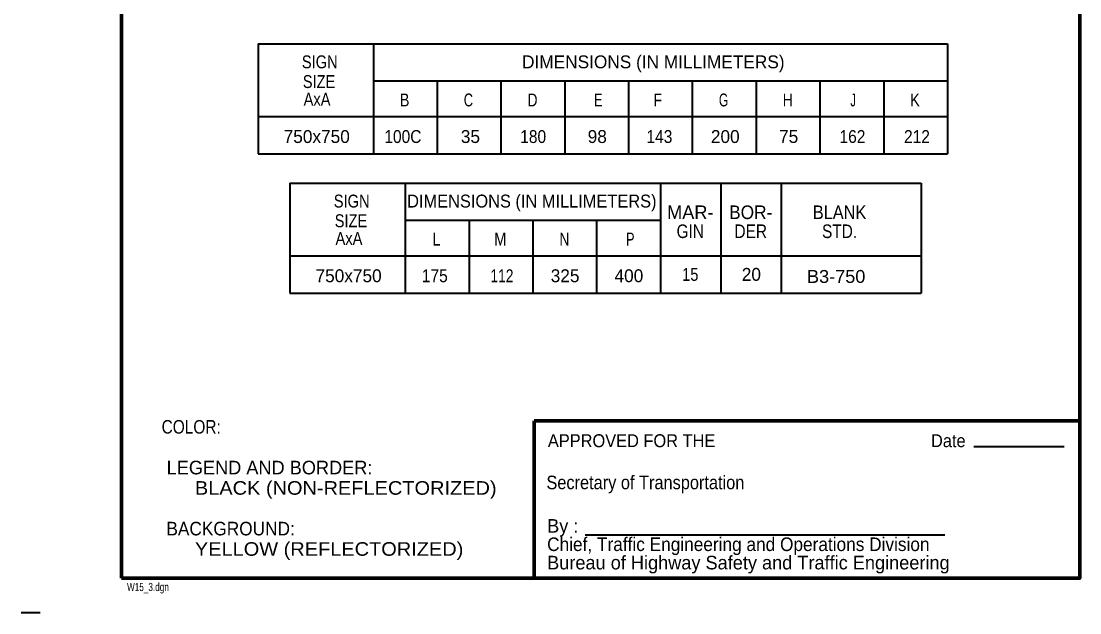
# Model space of a CAD drawing. Extents: x -0.018 to 0.195, y -0.006 to 0.263.
# Drawn here: x -0.0185 to 0.1765, y -0.0064 to 0.1026 of the extents above; entities that cross this region are included whole.
import ezdxf
from ezdxf.enums import TextEntityAlignment as Align

# ---------------------------------------------------------------- set-up
doc = ezdxf.new("R2010")
doc.units = 0
doc.header["$LTSCALE"] = 0.00096
doc.layers.add('1', color=7, linetype='Continuous', lineweight=25)
doc.layers.add('3', color=7, linetype='Continuous', lineweight=35)

msp = doc.modelspace()

# ---------------------------------------------------------------- linework, layer by layer
at = {"layer": '1', "lineweight": 70}
for q in [(0.1765, 0.029), (0.076, 0)]:
    msp.add_line((0.076, 0.029), q, dxfattribs=at)
at = {"layer": '1', "lineweight": 35}
for p, q in [((0.157, 0.02425), (0.17363, 0.02425)), ((0.08538, 0.008), (0.15163, 0.008)), ((-0.015, -0.00637), (-0.0185, -0.00637))]:
    msp.add_line(p, q, dxfattribs=at)
at = {"layer": '1', "lineweight": 70}
msp.add_lwpolyline([(0, 0), (0.1765, 0), (0.1765, 0.2565), (0, 0.2565)], close=True, dxfattribs=at)
at = {"layer": '3'}
for p, q in [((0.02513, 0.09838), (0.15213, 0.09838)), ((0.02513, 0.09838), (0.02513, 0.07812)), ((0.04637, 0.09838), (0.04637, 0.07812)), ((0.15213, 0.09838), (0.15213, 0.07812)), ((0.15213, 0.0915), (0.04637, 0.0915)), ((0.05813, 0.0915), (0.05813, 0.07812)), ((0.06988, 0.0915), (0.06988, 0.07812)), ((0.08163, 0.0915), (0.08163, 0.07812)), ((0.09337, 0.0915), (0.09337, 0.07812)), ((0.10512, 0.0915), (0.10512, 0.07812)), ((0.11688, 0.0915), (0.11688, 0.07812)), ((0.12862, 0.0915), (0.12862, 0.07812)), ((0.14037, 0.0915), (0.14037, 0.07812)), ((0.02513, 0.085), (0.15213, 0.085)), ((0.02513, 0.07812), (0.15213, 0.07812)), ((0.031, 0.07275), (0.14725, 0.07275)), ((0.031, 0.07275), (0.031, 0.0525)), ((0.05225, 0.07275), (0.05225, 0.0525)), ((0.09925, 0.07275), (0.09925, 0.0525)), ((0.11038, 0.07275), (0.11038, 0.0525)), ((0.1215, 0.07275), (0.1215, 0.0525)), ((0.14725, 0.07275), (0.14725, 0.0525)), ((0.09925, 0.06588), (0.05225, 0.06588)), ((0.064, 0.06588), (0.064, 0.0525)), ((0.07575, 0.06588), (0.07575, 0.0525)), ((0.0875, 0.06588), (0.0875, 0.0525)), ((0.031, 0.05937), (0.14725, 0.05937)), ((0.031, 0.0525), (0.14725, 0.0525))]:
    msp.add_line(p, q, dxfattribs=at)

# ---------------------------------------------------------------- texts
at = {"layer": '1'}
for s, height, width, p in [('COLOR:', 0.0025, 0.85, (0.00737, 0.02662)), ('      BLACK (NON-REFLECTORIZED)', 0.0025, 1.1, (0.00737, 0.01537)), ('Secretary of Transportation', 0.0025, 0.9, (0.07825, 0.01638)), (' BACKGROUND:', 0.0025, 0.95, (0.00737, 0.00788)), ('      YELLOW (REFLECTORIZED)', 0.0025, 1.1, (0.00737, 0.00413)), ('Chief, Traffic Engineering and Operations Division', 0.0025, 0.95, (0.07838, 0.005)), ('W15_3.dgn', 0.0015, 0.75, (0.001, -0.00237))]:
    msp.add_text(s, height=height, dxfattribs=dict(at, width=width)).set_placement(p)
at = {"layer": '1', "width": 0.95}
for s, p in [('APPROVED FOR THE', (0.09394, 0.02413)), ('Date ', (0.15269, 0.02413))]:
    msp.add_text(s, height=0.002375, dxfattribs=at).set_placement(p, align=Align.CENTER)
at = {"layer": '1'}
for s, p in [(' LEGEND AND BORDER:', (0.00737, 0.01912)), ('By :', (0.07838, 0.00838)), ('Bureau of Highway Safety and Traffic Engineering', (0.07838, 0.00162))]:
    msp.add_text(s, height=0.0025, dxfattribs=at).set_placement(p)
at = {"layer": '3'}
for s, height, width, p in [('SIGN', 0.002375, 0.85, (0.0365, 0.09388)), ('SIZE', 0.002375, 0.85, (0.03637, 0.09025)), ('AxA', 0.002375, 0.85, (0.036, 0.087)), ('B', 0.00237, 0.85, (0.05212, 0.08687)), ('C', 0.00237, 0.75, (0.06388, 0.08687)), ('D', 0.00237, 0.8, (0.07569, 0.08687)), ('E', 0.00237, 0.75, (0.08781, 0.08687)), ('F', 0.00237, 0.8, (0.09875, 0.08687)), ('G', 0.00237, 0.7, (0.11088, 0.08687)), ('H', 0.00237, 0.8, (0.12269, 0.08687)), ('J', 0.00237, 0.65, (0.13475, 0.08687)), ('K', 0.00237, 0.85, (0.14613, 0.08687)), ('100C', 0.002375, 0.9, (0.05181, 0.08013)), ('180', 0.002375, 0.9, (0.07581, 0.08013)), ('143', 0.002375, 0.9, (0.09906, 0.08013)), ('162', 0.002375, 0.9, (0.13462, 0.08013)), ('212', 0.002375, 0.9, (0.1465, 0.08013)), ('SIGN', 0.002375, 0.85, (0.04238, 0.06825)), ('DIMENSIONS (IN MILLIMETERS)', 0.002375, 0.95, (0.07556, 0.06825)), ('BOR-', 0.0025, 0.95, (0.11588, 0.06613)), ('BLANK', 0.0025, 0.9, (0.13225, 0.06613)), ('SIZE', 0.002375, 0.85, (0.04225, 0.06463)), ('GIN', 0.0025, 0.85, (0.10475, 0.06263)), ('DER', 0.0025, 0.85, (0.11588, 0.06263)), ('STD.', 0.0025, 0.85, (0.13225, 0.06263)), ('AxA', 0.002375, 0.85, (0.04188, 0.06137)), ('L', 0.00237, 0.85, (0.058, 0.06125)), ('M', 0.00237, 0.85, (0.06975, 0.06125)), ('N', 0.00237, 0.8, (0.08156, 0.06125)), ('P', 0.00237, 0.75, (0.09369, 0.06125)), ('175', 0.002375, 0.9, (0.05769, 0.0545)), ('112', 0.002375, 0.8, (0.07006, 0.0545)), ('15', 0.002375, 0.85, (0.10475, 0.05475)), ('B3-750', 0.002375, 1.05, (0.13162, 0.05437))]:
    msp.add_text(s, height=height, dxfattribs=dict(at, width=width)).set_placement(p, align=Align.CENTER)
for s, height, p in [('DIMENSIONS (IN MILLIMETERS)', 0.002375, (0.09794, 0.09388)), ('750x750', 0.002375, (0.03594, 0.08013)), ('35', 0.002375, (0.06425, 0.08013)), ('98', 0.002375, (0.08762, 0.08013)), ('200', 0.002375, (0.11119, 0.08013)), ('75', 0.002375, (0.12287, 0.08013)), ('MAR-', 0.0025, (0.10475, 0.06613)), ('750x750', 0.002375, (0.04181, 0.0545)), ('325', 0.002375, (0.08169, 0.0545)), ('400', 0.002375, (0.09344, 0.0545)), ('20', 0.002375, (0.116, 0.05475))]:
    msp.add_text(s, height=height, dxfattribs=at).set_placement(p, align=Align.CENTER)

doc.saveas('drawing.dxf')
